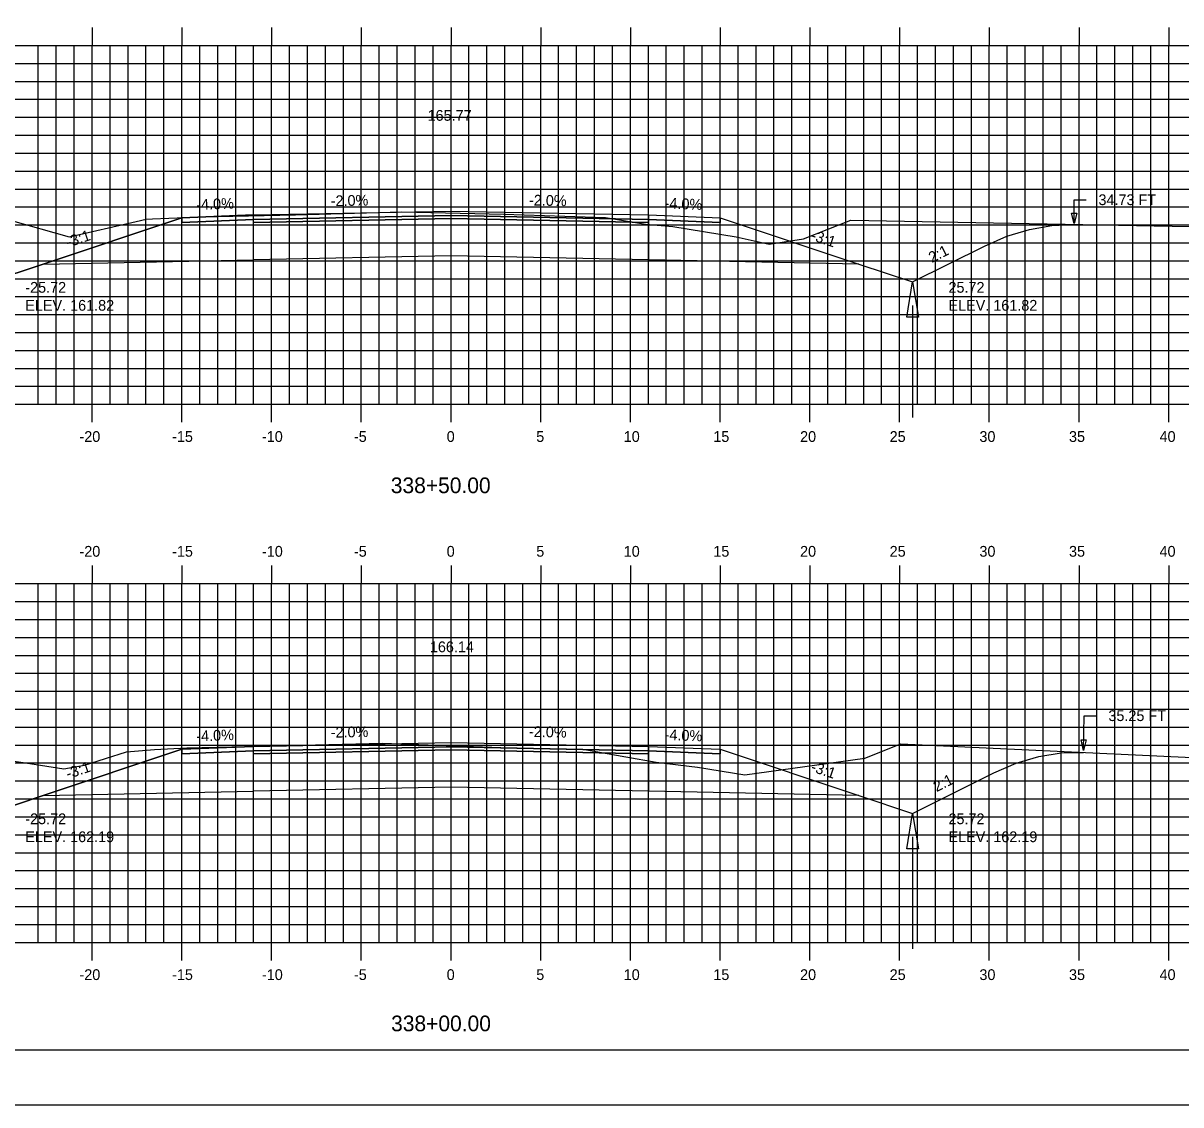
# Model space of a CAD drawing. Extents: x 1142533 to 1142703, y 608981 to 609091.
# Drawn here: x 1142592.2 to 1142656.7, y 608981.3 to 609041.6 of the extents above; entities that cross this region are included whole.
import ezdxf

# ---------------------------------------------------------------- set-up
doc = ezdxf.new("R2010")
doc.units = 0
for name, color, linetype in [('ANNOTATION', 7, 'Continuous'), ('BORDER', 7, 'Continuous'), ('D_Drainage_Ditch_Line', 7, 'Continuous'), ('D_Roadway_Centerline', 7, 'Continuous'), ('D_Roadway_Centerline_Text', 7, 'Continuous'), ('D_Roadway_Edge_Shoulder', 7, 'Continuous'), ('D_Roadway_Edge_TW', 7, 'Continuous'), ('D_Roadway_Pavement', 7, 'Continuous'), ('D_Roadway_SlopeLines', 7, 'Continuous'), ('D_Roadway_SubGrade', 7, 'Continuous'), ('D_Text_Standard', 7, 'Continuous'), ('H_V ANNOTATION', 7, 'Continuous'), ('MAJOR', 7, 'Continuous'), ('MINOR', 7, 'Continuous'), ('PLOT BOUNDARY', 7, 'Continuous'), ('S_Roadway_Centerline', 7, 'Continuous')]:
    doc.layers.add(name, color=color, linetype=linetype)

msp = doc.modelspace()

# ---------------------------------------------------------------- linework, layer by layer
for points in [[(1142580.286, 609030.994), (1142581.536, 609030.885), (1142582.786, 609030.628), (1142584.036, 609030.224), (1142585.286, 609029.673), (1142590.329, 609027.152), (1142593.329, 609028.152), (1142601.052, 609030.726), (1142601.053, 609030.726), (1142605.053, 609030.886), (1142616.053, 609031.106), (1142627.053, 609030.886), (1142631.053, 609030.726), (1142638.777, 609028.152), (1142641.777, 609027.152), (1142645.788, 609029.157), (1142647.038, 609029.701), (1142648.288, 609030.083), (1142649.538, 609030.303), (1142650.788, 609030.361)], [(1142581.032, 609000.945), (1142582.282, 609000.857), (1142583.532, 609000.615), (1142584.782, 609000.22), (1142586.032, 608999.672), (1142590.329, 608997.523), (1142593.329, 608998.523), (1142601.052, 609001.098), (1142601.053, 609001.098), (1142605.053, 609001.258), (1142616.053, 609001.478), (1142627.053, 609001.258), (1142631.053, 609001.098), (1142638.777, 608998.523), (1142641.777, 608997.523), (1142646.306, 608999.787), (1142647.556, 609000.327), (1142648.806, 609000.696), (1142650.056, 609000.894), (1142651.306, 609000.921)]]:
    msp.add_lwpolyline(points)
at = {"layer": 'BORDER'}
msp.add_lwpolyline([(1142541.054, 608984.335), (1142701.054, 608984.335), (1142701.054, 609089.335), (1142541.054, 609089.335)], close=True, dxfattribs=at)
at = {"layer": 'D_Drainage_Ditch_Line'}
for p, q in [((1142641.777, 609025.839), (1142641.777, 609019.596)), ((1142641.777, 608996.211), (1142641.777, 608989.967))]:
    msp.add_line(p, q, dxfattribs=at)
for points in [[(1142642.105, 609025.183), (1142641.449, 609025.183), (1142641.777, 609027.152)], [(1142642.105, 608995.555), (1142641.449, 608995.555), (1142641.777, 608997.523)]]:
    msp.add_lwpolyline(points, close=True, dxfattribs=at)
at = {"layer": 'D_Roadway_Edge_Shoulder'}
for points in [[(1142605.053, 609030.886), (1142601.053, 609030.726), (1142601.053, 609030.476), (1142605.053, 609030.636)], [(1142627.053, 609030.886), (1142631.053, 609030.726), (1142631.053, 609030.476), (1142627.053, 609030.636)], [(1142605.053, 609001.258), (1142601.053, 609001.098), (1142601.053, 609000.848), (1142605.053, 609001.008)], [(1142627.053, 609001.258), (1142631.053, 609001.098), (1142631.053, 609000.848), (1142627.053, 609001.008)]]:
    msp.add_lwpolyline(points, close=True, dxfattribs=at)
at = {"layer": 'D_Roadway_Edge_TW'}
for points in [[(1142605.053, 609030.636), (1142605.053, 609030.886), (1142616.053, 609031.106), (1142627.053, 609030.886), (1142627.053, 609030.636), (1142616.053, 609030.856)], [(1142605.053, 609001.008), (1142605.053, 609001.258), (1142616.053, 609001.478), (1142627.053, 609001.258), (1142627.053, 609001.008), (1142616.053, 609001.228)]]:
    msp.add_lwpolyline(points, close=True, dxfattribs=at)
at = {"layer": 'D_Roadway_Pavement'}
for points in [[(1142605.053, 609030.469), (1142605.053, 609030.636), (1142616.053, 609030.856), (1142627.053, 609030.636), (1142627.053, 609030.469), (1142616.053, 609030.689)], [(1142605.053, 609000.841), (1142605.053, 609001.008), (1142616.053, 609001.228), (1142627.053, 609001.008), (1142627.053, 609000.841), (1142616.053, 609001.061)]]:
    msp.add_lwpolyline(points, close=True, dxfattribs=at)
at = {"layer": 'D_Roadway_SlopeLines'}
for points in [[(1142641.777, 609027.152), (1142645.788, 609029.157), (1142647.038, 609029.701), (1142648.288, 609030.083), (1142649.538, 609030.303), (1142650.788, 609030.361)], [(1142593.329, 609028.152), (1142590.329, 609027.152)], [(1142638.777, 609028.152), (1142641.777, 609027.152)], [(1142641.777, 608997.523), (1142646.306, 608999.787), (1142647.556, 609000.327), (1142648.806, 609000.696), (1142650.056, 609000.894), (1142651.306, 609000.921)], [(1142593.329, 608998.523), (1142590.329, 608997.523)], [(1142638.777, 608998.523), (1142641.777, 608997.523)]]:
    msp.add_lwpolyline(points, dxfattribs=at)
at = {"layer": 'D_Roadway_SubGrade'}
for points in [[(1142605.053, 609030.469), (1142605.053, 609030.636), (1142601.053, 609030.476), (1142601.053, 609030.726), (1142601.052, 609030.726), (1142593.329, 609028.152), (1142605.053, 609028.386)], [(1142605.053, 609028.386), (1142605.053, 609030.469), (1142616.053, 609030.689), (1142627.053, 609030.469), (1142627.053, 609028.386), (1142616.053, 609028.606)], [(1142627.053, 609030.469), (1142627.053, 609030.636), (1142631.053, 609030.476), (1142631.053, 609030.726), (1142631.054, 609030.726), (1142638.777, 609028.152), (1142627.053, 609028.386)], [(1142605.053, 609000.841), (1142605.053, 609001.008), (1142601.053, 609000.848), (1142601.053, 609001.098), (1142601.052, 609001.098), (1142593.329, 608998.523), (1142605.053, 608998.758)], [(1142605.053, 608998.758), (1142605.053, 609000.841), (1142616.053, 609001.061), (1142627.053, 609000.841), (1142627.053, 608998.758), (1142616.053, 608998.978)], [(1142627.053, 609000.841), (1142627.053, 609001.008), (1142631.053, 609000.848), (1142631.053, 609001.098), (1142631.054, 609001.098), (1142638.777, 608998.523), (1142627.053, 608998.758)]]:
    msp.add_lwpolyline(points, close=True, dxfattribs=at)
at = {"layer": 'D_Text_Standard'}
for points in [[(1142650.788, 609030.407), (1142650.777, 609031.735), (1142651.457, 609031.735)], [(1142651.306, 609001.037), (1142651.33, 609002.973), (1142652.01, 609002.973)]]:
    msp.add_lwpolyline(points, dxfattribs=at)
for points in [[(1142650.788, 609030.407), (1142650.638, 609030.988), (1142650.929, 609030.99)], [(1142651.306, 609001.037), (1142651.167, 609001.621), (1142651.458, 609001.618)]]:
    msp.add_lwpolyline(points, close=True, dxfattribs=at)
at = {"layer": 'MAJOR'}
for p, q in [((1142596.053, 609041.337), (1142596.053, 609040.335)), ((1142601.053, 609041.337), (1142601.053, 609040.335)), ((1142606.053, 609041.337), (1142606.053, 609040.335)), ((1142611.053, 609041.337), (1142611.053, 609040.335)), ((1142616.053, 609041.337), (1142616.053, 609040.335)), ((1142621.053, 609041.337), (1142621.053, 609040.335)), ((1142626.053, 609041.337), (1142626.053, 609040.335)), ((1142631.053, 609041.337), (1142631.053, 609040.335)), ((1142636.053, 609041.337), (1142636.053, 609040.335)), ((1142641.053, 609041.337), (1142641.053, 609040.335)), ((1142646.053, 609041.337), (1142646.053, 609040.335)), ((1142651.053, 609041.337), (1142651.053, 609040.335)), ((1142656.053, 609041.337), (1142656.053, 609040.335)), ((1142546.053, 609040.335), (1142686.053, 609040.335)), ((1142546.053, 609040.335), (1142686.053, 609040.335)), ((1142596.053, 609020.335), (1142596.053, 609040.335)), ((1142601.053, 609020.335), (1142601.053, 609040.335)), ((1142606.053, 609020.335), (1142606.053, 609040.335)), ((1142611.053, 609020.335), (1142611.053, 609040.335)), ((1142616.053, 609020.335), (1142616.053, 609040.335)), ((1142621.053, 609020.335), (1142621.053, 609040.335)), ((1142626.053, 609020.335), (1142626.053, 609040.335)), ((1142631.053, 609020.335), (1142631.053, 609040.335)), ((1142636.053, 609020.335), (1142636.053, 609040.335)), ((1142641.053, 609020.335), (1142641.053, 609040.335)), ((1142646.053, 609020.335), (1142646.053, 609040.335)), ((1142651.053, 609020.335), (1142651.053, 609040.335)), ((1142656.053, 609020.335), (1142656.053, 609040.335)), ((1142546.053, 609035.335), (1142686.053, 609035.335)), ((1142546.053, 609030.335), (1142686.053, 609030.335)), ((1142546.053, 609025.335), (1142686.053, 609025.335)), ((1142546.053, 609020.335), (1142686.053, 609020.335)), ((1142546.053, 609020.335), (1142686.053, 609020.335)), ((1142596.053, 609019.333), (1142596.053, 609020.335)), ((1142601.053, 609019.333), (1142601.053, 609020.335)), ((1142606.053, 609019.333), (1142606.053, 609020.335)), ((1142611.053, 609019.333), (1142611.053, 609020.335)), ((1142616.053, 609019.333), (1142616.053, 609020.335)), ((1142621.053, 609019.333), (1142621.053, 609020.335)), ((1142626.053, 609019.333), (1142626.053, 609020.335)), ((1142631.053, 609019.333), (1142631.053, 609020.335)), ((1142636.053, 609019.333), (1142636.053, 609020.335)), ((1142641.053, 609019.333), (1142641.053, 609020.335)), ((1142646.053, 609019.333), (1142646.053, 609020.335)), ((1142651.053, 609019.333), (1142651.053, 609020.335)), ((1142656.053, 609019.333), (1142656.053, 609020.335)), ((1142596.053, 609011.337), (1142596.053, 609010.335)), ((1142601.053, 609011.337), (1142601.053, 609010.335)), ((1142606.053, 609011.337), (1142606.053, 609010.335)), ((1142611.053, 609011.337), (1142611.053, 609010.335)), ((1142616.053, 609011.337), (1142616.053, 609010.335)), ((1142621.053, 609011.337), (1142621.053, 609010.335)), ((1142626.053, 609011.337), (1142626.053, 609010.335)), ((1142631.053, 609011.337), (1142631.053, 609010.335)), ((1142636.053, 609011.337), (1142636.053, 609010.335)), ((1142641.053, 609011.337), (1142641.053, 609010.335)), ((1142646.053, 609011.337), (1142646.053, 609010.335)), ((1142651.053, 609011.337), (1142651.053, 609010.335)), ((1142656.053, 609011.337), (1142656.053, 609010.335)), ((1142546.053, 609010.335), (1142686.053, 609010.335)), ((1142546.053, 609010.335), (1142686.053, 609010.335)), ((1142596.053, 608990.335), (1142596.053, 609010.335)), ((1142601.053, 608990.335), (1142601.053, 609010.335)), ((1142606.053, 608990.335), (1142606.053, 609010.335)), ((1142611.053, 608990.335), (1142611.053, 609010.335)), ((1142616.053, 608990.335), (1142616.053, 609010.335)), ((1142621.053, 608990.335), (1142621.053, 609010.335)), ((1142626.053, 608990.335), (1142626.053, 609010.335)), ((1142631.053, 608990.335), (1142631.053, 609010.335)), ((1142636.053, 608990.335), (1142636.053, 609010.335)), ((1142641.053, 608990.335), (1142641.053, 609010.335)), ((1142646.053, 608990.335), (1142646.053, 609010.335)), ((1142651.053, 608990.335), (1142651.053, 609010.335)), ((1142656.053, 608990.335), (1142656.053, 609010.335)), ((1142546.053, 609005.335), (1142686.053, 609005.335)), ((1142546.053, 609000.335), (1142686.053, 609000.335)), ((1142546.053, 608995.335), (1142686.053, 608995.335)), ((1142546.053, 608990.335), (1142686.053, 608990.335)), ((1142546.053, 608990.335), (1142686.053, 608990.335)), ((1142596.053, 608989.333), (1142596.053, 608990.335)), ((1142601.053, 608989.333), (1142601.053, 608990.335)), ((1142606.053, 608989.333), (1142606.053, 608990.335)), ((1142611.053, 608989.333), (1142611.053, 608990.335)), ((1142616.053, 608989.333), (1142616.053, 608990.335)), ((1142621.053, 608989.333), (1142621.053, 608990.335)), ((1142626.053, 608989.333), (1142626.053, 608990.335)), ((1142631.053, 608989.333), (1142631.053, 608990.335)), ((1142636.053, 608989.333), (1142636.053, 608990.335)), ((1142641.053, 608989.333), (1142641.053, 608990.335)), ((1142646.053, 608989.333), (1142646.053, 608990.335)), ((1142651.053, 608989.333), (1142651.053, 608990.335)), ((1142656.053, 608989.333), (1142656.053, 608990.335))]:
    msp.add_line(p, q, dxfattribs=at)
at = {"layer": 'MINOR'}
for p, q in [((1142593.053, 609020.335), (1142593.053, 609040.335)), ((1142594.053, 609020.335), (1142594.053, 609040.335)), ((1142595.053, 609020.335), (1142595.053, 609040.335)), ((1142597.053, 609020.335), (1142597.053, 609040.335)), ((1142598.053, 609020.335), (1142598.053, 609040.335)), ((1142599.053, 609020.335), (1142599.053, 609040.335)), ((1142600.053, 609020.335), (1142600.053, 609040.335)), ((1142602.053, 609020.335), (1142602.053, 609040.335)), ((1142603.053, 609020.335), (1142603.053, 609040.335)), ((1142604.053, 609020.335), (1142604.053, 609040.335)), ((1142605.053, 609020.335), (1142605.053, 609040.335)), ((1142607.053, 609020.335), (1142607.053, 609040.335)), ((1142608.053, 609020.335), (1142608.053, 609040.335)), ((1142609.053, 609020.335), (1142609.053, 609040.335)), ((1142610.053, 609020.335), (1142610.053, 609040.335)), ((1142612.053, 609020.335), (1142612.053, 609040.335)), ((1142613.053, 609020.335), (1142613.053, 609040.335)), ((1142614.053, 609020.335), (1142614.053, 609040.335)), ((1142615.053, 609020.335), (1142615.053, 609040.335)), ((1142617.053, 609020.335), (1142617.053, 609040.335)), ((1142618.053, 609020.335), (1142618.053, 609040.335)), ((1142619.053, 609020.335), (1142619.053, 609040.335)), ((1142620.053, 609020.335), (1142620.053, 609040.335)), ((1142622.053, 609020.335), (1142622.053, 609040.335)), ((1142623.053, 609020.335), (1142623.053, 609040.335)), ((1142624.053, 609020.335), (1142624.053, 609040.335)), ((1142625.053, 609020.335), (1142625.053, 609040.335)), ((1142627.053, 609020.335), (1142627.053, 609040.335)), ((1142628.053, 609020.335), (1142628.053, 609040.335)), ((1142629.053, 609020.335), (1142629.053, 609040.335)), ((1142630.053, 609020.335), (1142630.053, 609040.335)), ((1142632.053, 609020.335), (1142632.053, 609040.335)), ((1142633.053, 609020.335), (1142633.053, 609040.335)), ((1142634.053, 609020.335), (1142634.053, 609040.335)), ((1142635.053, 609020.335), (1142635.053, 609040.335)), ((1142637.053, 609020.335), (1142637.053, 609040.335)), ((1142638.053, 609020.335), (1142638.053, 609040.335)), ((1142639.053, 609020.335), (1142639.053, 609040.335)), ((1142640.053, 609020.335), (1142640.053, 609040.335)), ((1142642.053, 609020.335), (1142642.053, 609040.335)), ((1142643.053, 609020.335), (1142643.053, 609040.335)), ((1142644.053, 609020.335), (1142644.053, 609040.335)), ((1142645.053, 609020.335), (1142645.053, 609040.335)), ((1142647.053, 609020.335), (1142647.053, 609040.335)), ((1142648.053, 609020.335), (1142648.053, 609040.335)), ((1142649.053, 609020.335), (1142649.053, 609040.335)), ((1142650.053, 609020.335), (1142650.053, 609040.335)), ((1142652.053, 609020.335), (1142652.053, 609040.335)), ((1142653.053, 609020.335), (1142653.053, 609040.335)), ((1142654.053, 609020.335), (1142654.053, 609040.335)), ((1142655.053, 609020.335), (1142655.053, 609040.335)), ((1142546.053, 609039.335), (1142686.053, 609039.335)), ((1142546.053, 609038.335), (1142686.053, 609038.335)), ((1142546.053, 609037.335), (1142686.053, 609037.335)), ((1142546.053, 609036.335), (1142686.053, 609036.335)), ((1142546.053, 609034.335), (1142686.053, 609034.335)), ((1142546.053, 609033.335), (1142686.053, 609033.335)), ((1142546.053, 609032.335), (1142686.053, 609032.335)), ((1142546.053, 609031.335), (1142686.053, 609031.335)), ((1142546.053, 609029.335), (1142686.053, 609029.335)), ((1142546.053, 609028.335), (1142686.053, 609028.335)), ((1142546.053, 609027.335), (1142686.053, 609027.335)), ((1142546.053, 609026.335), (1142686.053, 609026.335)), ((1142546.053, 609024.335), (1142686.053, 609024.335)), ((1142546.053, 609023.335), (1142686.053, 609023.335)), ((1142546.053, 609022.335), (1142686.053, 609022.335)), ((1142546.053, 609021.335), (1142686.053, 609021.335)), ((1142593.053, 608990.335), (1142593.053, 609010.335)), ((1142594.053, 608990.335), (1142594.053, 609010.335)), ((1142595.053, 608990.335), (1142595.053, 609010.335)), ((1142597.053, 608990.335), (1142597.053, 609010.335)), ((1142598.053, 608990.335), (1142598.053, 609010.335)), ((1142599.053, 608990.335), (1142599.053, 609010.335)), ((1142600.053, 608990.335), (1142600.053, 609010.335)), ((1142602.053, 608990.335), (1142602.053, 609010.335)), ((1142603.053, 608990.335), (1142603.053, 609010.335)), ((1142604.053, 608990.335), (1142604.053, 609010.335)), ((1142605.053, 608990.335), (1142605.053, 609010.335)), ((1142607.053, 608990.335), (1142607.053, 609010.335)), ((1142608.053, 608990.335), (1142608.053, 609010.335)), ((1142609.053, 608990.335), (1142609.053, 609010.335)), ((1142610.053, 608990.335), (1142610.053, 609010.335)), ((1142612.053, 608990.335), (1142612.053, 609010.335)), ((1142613.053, 608990.335), (1142613.053, 609010.335)), ((1142614.053, 608990.335), (1142614.053, 609010.335)), ((1142615.053, 608990.335), (1142615.053, 609010.335)), ((1142617.053, 608990.335), (1142617.053, 609010.335)), ((1142618.053, 608990.335), (1142618.053, 609010.335)), ((1142619.053, 608990.335), (1142619.053, 609010.335)), ((1142620.053, 608990.335), (1142620.053, 609010.335)), ((1142622.053, 608990.335), (1142622.053, 609010.335)), ((1142623.053, 608990.335), (1142623.053, 609010.335)), ((1142624.053, 608990.335), (1142624.053, 609010.335)), ((1142625.053, 608990.335), (1142625.053, 609010.335)), ((1142627.053, 608990.335), (1142627.053, 609010.335)), ((1142628.053, 608990.335), (1142628.053, 609010.335)), ((1142629.053, 608990.335), (1142629.053, 609010.335)), ((1142630.053, 608990.335), (1142630.053, 609010.335)), ((1142632.053, 608990.335), (1142632.053, 609010.335)), ((1142633.053, 608990.335), (1142633.053, 609010.335)), ((1142634.053, 608990.335), (1142634.053, 609010.335)), ((1142635.053, 608990.335), (1142635.053, 609010.335)), ((1142637.053, 608990.335), (1142637.053, 609010.335)), ((1142638.053, 608990.335), (1142638.053, 609010.335)), ((1142639.053, 608990.335), (1142639.053, 609010.335)), ((1142640.053, 608990.335), (1142640.053, 609010.335)), ((1142642.053, 608990.335), (1142642.053, 609010.335)), ((1142643.053, 608990.335), (1142643.053, 609010.335)), ((1142644.053, 608990.335), (1142644.053, 609010.335)), ((1142645.053, 608990.335), (1142645.053, 609010.335)), ((1142647.053, 608990.335), (1142647.053, 609010.335)), ((1142648.053, 608990.335), (1142648.053, 609010.335)), ((1142649.053, 608990.335), (1142649.053, 609010.335)), ((1142650.053, 608990.335), (1142650.053, 609010.335)), ((1142652.053, 608990.335), (1142652.053, 609010.335)), ((1142653.053, 608990.335), (1142653.053, 609010.335)), ((1142654.053, 608990.335), (1142654.053, 609010.335)), ((1142655.053, 608990.335), (1142655.053, 609010.335)), ((1142546.053, 609009.335), (1142686.053, 609009.335)), ((1142546.053, 609008.335), (1142686.053, 609008.335)), ((1142546.053, 609007.335), (1142686.053, 609007.335)), ((1142546.053, 609006.335), (1142686.053, 609006.335)), ((1142546.053, 609004.335), (1142686.053, 609004.335)), ((1142546.053, 609003.335), (1142686.053, 609003.335)), ((1142546.053, 609002.335), (1142686.053, 609002.335)), ((1142546.053, 609001.335), (1142686.053, 609001.335)), ((1142546.053, 608999.335), (1142686.053, 608999.335)), ((1142546.053, 608998.335), (1142686.053, 608998.335)), ((1142546.053, 608997.335), (1142686.053, 608997.335)), ((1142546.053, 608996.335), (1142686.053, 608996.335)), ((1142546.053, 608994.335), (1142686.053, 608994.335)), ((1142546.053, 608993.335), (1142686.053, 608993.335)), ((1142546.053, 608992.335), (1142686.053, 608992.335)), ((1142546.053, 608991.335), (1142686.053, 608991.335))]:
    msp.add_line(p, q, dxfattribs=at)
at = {"layer": 'PLOT BOUNDARY'}
msp.add_lwpolyline([(1142532.96, 608981.276), (1142702.96, 608981.276), (1142702.96, 609091.276), (1142532.96, 609091.276)], close=True, dxfattribs=at)
at = {"layer": 'S_Roadway_Centerline'}
for points in [[(1142546.053, 609031.583), (1142570.408, 609031.275), (1142587.086, 609030.801), (1142590.294, 609030.814), (1142591.488, 609030.599), (1142594.777, 609029.667), (1142598.5, 609030.516), (1142599.061, 609030.651), (1142599.412, 609030.68), (1142602.144, 609030.775), (1142607.389, 609030.886), (1142613.313, 609031.057), (1142619.003, 609030.938), (1142624.666, 609030.747), (1142626.894, 609030.371), (1142628.418, 609030.242), (1142631.945, 609029.672), (1142633.786, 609029.252), (1142635.704, 609029.565), (1142638.328, 609030.59), (1142669.168, 609030.024), (1142672.845, 609029.979), (1142676.772, 609029.961), (1142686.053, 609029.887)], [(1142546.053, 609001.213), (1142548.7, 609001.192), (1142571.996, 609000.966), (1142582.291, 609000.942), (1142589.042, 609000.829), (1142592.574, 609000.311), (1142594.485, 609000.01), (1142595.627, 609000.223), (1142597.969, 609000.962), (1142599.526, 609001.079), (1142601.324, 609001.178), (1142605.502, 609001.265), (1142612.227, 609001.447), (1142618.838, 609001.201), (1142623.394, 609001.103), (1142625.788, 609000.67), (1142627.482, 609000.383), (1142629.79, 609000.093), (1142632.431, 608999.666), (1142639.118, 609000.611), (1142641.121, 609001.396), (1142656.974, 609000.657), (1142667.405, 609000.249), (1142686.053, 609000.083)]]:
    msp.add_lwpolyline(points, dxfattribs=at)

# ---------------------------------------------------------------- texts
at = {"layer": 'ANNOTATION'}
for s, rotation, p in [('-2.0%', 1.14576, (1142609.356, 609031.372)), ('-2.0%', 358.85424, (1142620.396, 609031.42)), ('-4.0%', 2.29061, (1142601.869, 609031.16)), ('-4.0%', 357.70939, (1142627.949, 609031.251)), ('-3:1', 18.43482, (1142594.708, 609029.065)), ('-3:1', 341.56521, (1142636.065, 609029.51)), ('2:1', 26.56505, (1142642.855, 609028.209)), ('-2.0%', 1.14576, (1142609.356, 609001.744)), ('-2.0%', 358.85424, (1142620.396, 609001.791)), ('-4.0%', 2.29061, (1142601.869, 609001.531)), ('-4.0%', 357.70939, (1142627.949, 609001.623)), ('-3:1', 18.43482, (1142594.708, 608999.437)), ('-3:1', 341.56521, (1142636.065, 608999.881)), ('2:1', 26.56505, (1142643.114, 608998.71))]:
    msp.add_text(s, height=0.6, rotation=rotation, dxfattribs=at).set_placement(p)
at = {"layer": 'D_Roadway_Centerline'}
for s, p in [('C', (1142616.048, 609031.106)), ('L', (1142616.053, 609031.099)), ('C', (1142616.048, 609001.478)), ('L', (1142616.053, 609001.47))]:
    msp.add_text(s, height=0.0146, dxfattribs=at).set_placement(p)
at = {"layer": 'D_Roadway_Centerline_Text'}
for s, p in [('165.77', (1142614.748, 609036.138)), ('166.14', (1142614.876, 609006.51))]:
    msp.add_text(s, height=0.6, dxfattribs=at).set_placement(p)
at = {"layer": 'D_Text_Standard'}
for s, p in [('34.73 FT', (1142652.137, 609031.435)), ('-25.72', (1142592.329, 609026.552)), ('25.72', (1142643.777, 609026.552)), ('ELEV. 161.82', (1142592.329, 609025.55)), ('ELEV. 161.82', (1142643.777, 609025.55)), ('35.25 FT', (1142652.69, 609002.673)), ('-25.72', (1142592.329, 608996.923)), ('25.72', (1142643.777, 608996.923)), ('ELEV. 162.19', (1142592.329, 608995.921)), ('ELEV. 162.19', (1142643.777, 608995.921))]:
    msp.add_text(s, height=0.6, dxfattribs=at).set_placement(p)
at = {"layer": 'H_V ANNOTATION'}
for s, height, p in [('-20', 0.6, (1142595.347, 609018.235)), ('-15', 0.6, (1142600.51, 609018.235)), ('-10', 0.6, (1142605.518, 609018.235)), ('-5', 0.6, (1142610.644, 609018.235)), ('0', 0.6, (1142615.813, 609018.235)), ('5', 0.6, (1142620.804, 609018.235)), ('10', 0.6, (1142625.679, 609018.235)), ('15', 0.6, (1142630.671, 609018.235)), ('20', 0.6, (1142635.507, 609018.235)), ('25', 0.6, (1142640.499, 609018.235)), ('30', 0.6, (1142645.502, 609018.235)), ('35', 0.6, (1142650.494, 609018.235)), ('40', 0.6, (1142655.54, 609018.235)), ('338+50.00', 0.875, (1142612.698, 609015.378)), ('-20', 0.6, (1142595.347, 609011.835)), ('-15', 0.6, (1142600.51, 609011.835)), ('-10', 0.6, (1142605.518, 609011.835)), ('-5', 0.6, (1142610.644, 609011.835)), ('0', 0.6, (1142615.813, 609011.835)), ('5', 0.6, (1142620.804, 609011.835)), ('10', 0.6, (1142625.679, 609011.835)), ('15', 0.6, (1142630.671, 609011.835)), ('20', 0.6, (1142635.507, 609011.835)), ('25', 0.6, (1142640.499, 609011.835)), ('30', 0.6, (1142645.502, 609011.835)), ('35', 0.6, (1142650.494, 609011.835)), ('40', 0.6, (1142655.54, 609011.835)), ('-20', 0.6, (1142595.347, 608988.235)), ('-15', 0.6, (1142600.51, 608988.235)), ('-10', 0.6, (1142605.518, 608988.235)), ('-5', 0.6, (1142610.644, 608988.235)), ('0', 0.6, (1142615.813, 608988.235)), ('5', 0.6, (1142620.804, 608988.235)), ('10', 0.6, (1142625.679, 608988.235)), ('15', 0.6, (1142630.671, 608988.235)), ('20', 0.6, (1142635.507, 608988.235)), ('25', 0.6, (1142640.499, 608988.235)), ('30', 0.6, (1142645.502, 608988.235)), ('35', 0.6, (1142650.494, 608988.235)), ('40', 0.6, (1142655.54, 608988.235)), ('338+00.00', 0.875, (1142612.714, 608985.378))]:
    msp.add_text(s, height=height, dxfattribs=at).set_placement(p)
at = {"layer": 'S_Roadway_Centerline'}
for s, p in [('L', (1142613.304, 609031.05)), ('C', (1142613.308, 609031.057)), ('L', (1142612.219, 609001.44)), ('C', (1142612.222, 609001.447))]:
    msp.add_text(s, height=0.0146, dxfattribs=at).set_placement(p)

doc.saveas('drawing.dxf')
